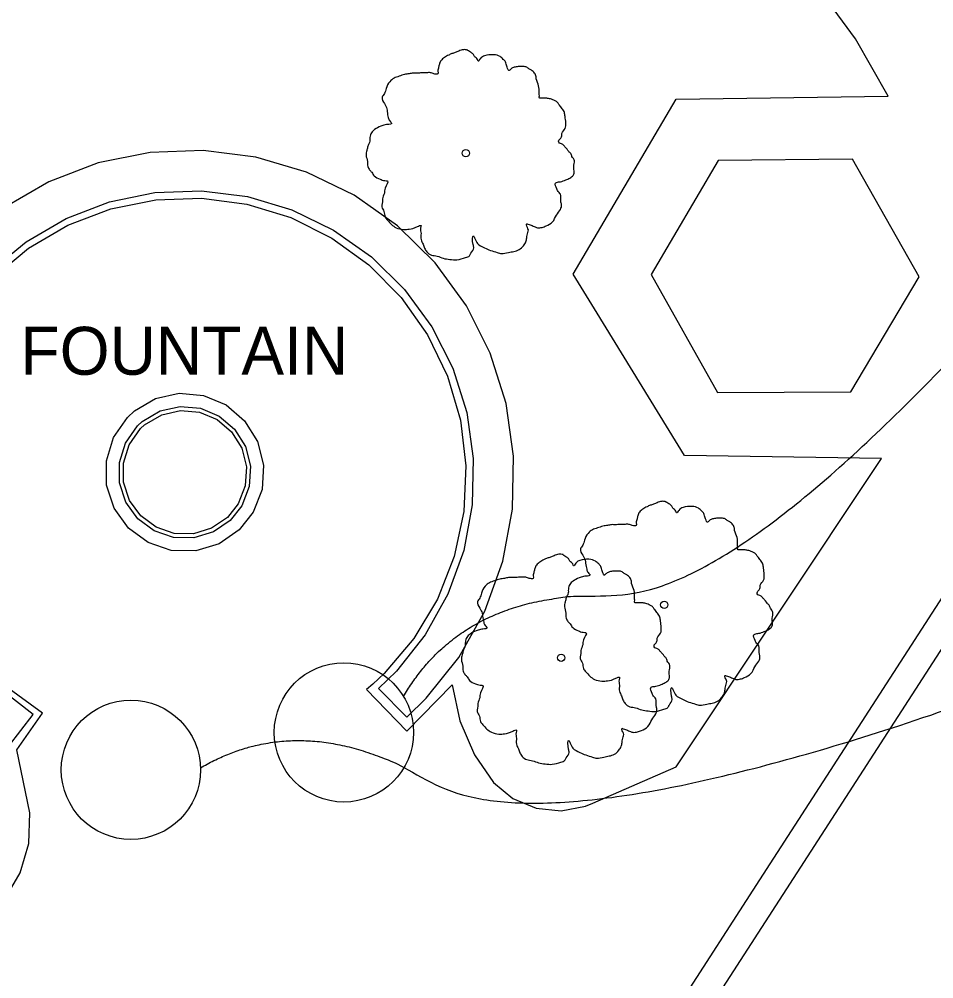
# Model space of a CAD drawing. Extents: x 2161152 to 2175754, y 602179 to 617749.
# Drawn here: x 2162210.9 to 2162258.6, y 604438.6 to 604488.6 of the extents above; entities that cross this region are included whole.
import ezdxf

# ---------------------------------------------------------------- set-up
doc = ezdxf.new("R2010")
doc.units = 0
for name, color, linetype in [('RD_EX_BldgApp', 7, 'Continuous'), ('RD_EX_BldgApp_Flagpole', 7, 'Continuous'), ('RD_EX_Conc_Curb', 7, 'Continuous'), ('RD_EX_Conc_Gutter', 7, 'Continuous'), ('RD_EX_Conc_Sidewalk', 7, 'Continuous'), ('RD_EX_H2O', 7, 'Continuous'), ('RD_EX_Misc_Golf_Cartpath', 7, 'Continuous'), ('RD_EX_VEG', 7, 'Continuous'), ('RD_EX_Wall', 7, 'Continuous')]:
    doc.layers.add(name, color=color, linetype=linetype)

msp = doc.modelspace()

# ---------------------------------------------------------------- linework, layer by layer
at = {"layer": 'RD_EX_BldgApp'}
msp.add_lwpolyline([(2162243.863, 604475.311), (2162247.306, 604469.159), (2162254.276, 604469.198), (2162257.836, 604475.18), (2162254.354, 604481.315), (2162247.346, 604481.257), (2162243.863, 604475.311)], dxfattribs=at)
at = {"layer": 'RD_EX_BldgApp_Flagpole'}
for centre in [(2162227.831, 604451.442), (2162216.724, 604449.493)]:
    msp.add_circle(centre, 3.63, dxfattribs=at)
for points in [[(2162230.941, 604453.313), (2162234.106, 604458.743), (2162249.321, 604458.429), (2162266.88, 604479.198)], [(2162220.352, 604449.592), (2162225.779, 604452.763), (2162238.871, 604445.006), (2162264.375, 604454.452)]]:
    msp.add_open_spline(points, degree=2, dxfattribs=at)
at = {"layer": 'RD_EX_Conc_Curb'}
msp.add_lwpolyline([(2162240.871, 604430.352), (2162249.525, 604443.766), (2162268.986, 604473.868)], dxfattribs=at)
at = {"layer": 'RD_EX_Conc_Gutter'}
msp.add_lwpolyline([(2162338.896, 604578.859), (2162334.64, 604572.384), (2162329.631, 604564.647), (2162322.947, 604554.413), (2162316.413, 604544.306), (2162296.019, 604512.784), (2162288.632, 604501.472), (2162280.136, 604488.331), (2162270.18, 604473.091), (2162250.721, 604442.993), (2162242.043, 604429.589), (2162236.596, 604421.216), (2162236.323, 604420.826), (2162236.31, 604420.722), (2162236.347, 604420.624), (2162236.488, 604420.501), (2162244.988, 604420.081), (2162253.595, 604419.765), (2162254.868, 604419.339), (2162256.485, 604417.99), (2162252.027, 604411.045), (2162237.228, 604388.179), (2162236.054, 604388.939)], dxfattribs=at)
at = {"layer": 'RD_EX_Conc_Sidewalk'}
for points in [[(2162209.54, 604475.147), (2162211.378, 604476.675), (2162213.442, 604477.881), (2162215.676, 604478.731), (2162218.019, 604479.203), (2162220.408, 604479.283), (2162222.778, 604478.97), (2162225.064, 604478.273), (2162227.205, 604477.209), (2162229.141, 604475.808), (2162230.822, 604474.108), (2162232.2, 604472.156), (2162233.239, 604470.003), (2162233.91, 604467.709), (2162234.195, 604465.337), (2162234.087, 604462.949), (2162233.588, 604460.611), (2162232.712, 604458.388), (2162231.483, 604456.338), (2162229.934, 604454.518), (2162229.336, 604453.955), (2162229.014, 604453.683), (2162231.113, 604451.512), (2162233.483, 604453.925), (2162233.875, 604452.038), (2162234.641, 604450.271), (2162235.642, 604448.824), (2162236.644, 604447.995), (2162237.851, 604447.49), (2162239.154, 604447.355), (2162240.436, 604447.602), (2162240.816, 604447.756), (2162245.163, 604449.641), (2162255.861, 604465.725), (2162245.597, 604465.872), (2162241.043, 604473.286), (2162239.785, 604475.317), (2162245.164, 604484.453), (2162256.222, 604484.598), (2162254.514, 604487.589), (2162252.478, 604490.366)], [(2162210.144, 604442.758), (2162210.952, 604444.128), (2162211.399, 604445.653), (2162211.459, 604447.242), (2162210.773, 604450.538), (2162212.11, 604452.437), (2162210.183, 604453.851)]]:
    msp.add_lwpolyline(points, dxfattribs=at)
at = {"layer": 'RD_EX_H2O'}
msp.add_lwpolyline([(2162221.76, 604462.649), (2162220.936, 604462.085), (2162219.982, 604461.798), (2162218.986, 604461.815), (2162218.042, 604462.134), (2162217.239, 604462.725), (2162216.655, 604463.531), (2162216.343, 604464.478), (2162216.334, 604465.474), (2162216.628, 604466.425), (2162217.222, 604467.278), (2162217.437, 604467.478), (2162218.332, 604468.002), (2162219.304, 604468.221), (2162220.297, 604468.134), (2162221.217, 604467.749), (2162221.975, 604467.103), (2162222.502, 604466.256), (2162222.746, 604465.29), (2162222.684, 604464.296), (2162222.322, 604463.362), (2162221.76, 604462.649)], dxfattribs=at)
at = {"layer": 'RD_EX_VEG'}
for centre, radius in [((2162234.19, 604481.631), 0.188), ((2162234.181, 604481.616), 0.000075), ((2162244.536, 604458.09), 0.188), ((2162244.526, 604458.076), 0.000075), ((2162239.164, 604455.332), 0.188), ((2162239.154, 604455.317), 0.000075)]:
    msp.add_circle(centre, radius, dxfattribs=at)
for points in [[(2162234.289, 604487.006), (2162234.065, 604487.025), (2162233.821, 604486.95), (2162233.633, 604486.875), (2162233.465, 604486.819), (2162233.296, 604486.744), (2162233.071, 604486.612), (2162232.903, 604486.462), (2162232.809, 604486.275), (2162232.771, 604486.106), (2162232.734, 604485.9), (2162232.734, 604485.769), (2162232.64, 604485.75), (2162232.528, 604485.769), (2162232.34, 604485.825), (2162232.153, 604485.825), (2162231.965, 604485.825), (2162231.703, 604485.806), (2162231.441, 604485.806), (2162231.235, 604485.769), (2162230.991, 604485.732), (2162230.71, 604485.638), (2162230.447, 604485.544), (2162230.222, 604485.357), (2162230.035, 604485.001), (2162229.941, 604484.738), (2162229.829, 604484.551), (2162229.941, 604484.213), (2162230.073, 604483.951), (2162230.091, 604483.801), (2162230.147, 604483.483), (2162230.222, 604483.314), (2162230.316, 604483.164), (2162230.26, 604483.145), (2162229.979, 604483.108), (2162229.754, 604483.033), (2162229.435, 604482.864), (2162229.267, 604482.695), (2162229.192, 604482.452), (2162229.173, 604482.189), (2162229.098, 604482.039), (2162229.042, 604481.833), (2162229.023, 604481.777), (2162228.985, 604481.533), (2162229.06, 604481.196), (2162229.079, 604480.934), (2162229.173, 604480.765), (2162229.285, 604480.634), (2162229.417, 604480.446), (2162229.716, 604480.278), (2162229.96, 604480.203), (2162230.11, 604480.184), (2162229.979, 604479.809), (2162229.941, 604479.547), (2162229.848, 604479.247), (2162229.848, 604479.191), (2162229.81, 604478.835), (2162229.923, 604478.591), (2162229.979, 604478.31), (2162230.11, 604478.141), (2162230.316, 604477.916), (2162230.56, 604477.748), (2162230.935, 604477.654), (2162231.235, 604477.673), (2162231.666, 604477.804), (2162231.853, 604477.86), (2162231.834, 604477.729), (2162231.853, 604477.448), (2162231.853, 604477.129), (2162231.965, 604476.885), (2162232.04, 604476.679), (2162232.153, 604476.492), (2162232.397, 604476.323), (2162232.696, 604476.267), (2162233.015, 604476.154), (2162233.352, 604476.098), (2162233.727, 604476.079), (2162234.177, 604476.192), (2162234.383, 604476.286), (2162234.458, 604476.417), (2162234.608, 604476.698), (2162234.571, 604476.867), (2162234.589, 604477.316), (2162234.664, 604477.185), (2162234.795, 604476.923), (2162235.17, 604476.698), (2162235.47, 604476.567), (2162235.826, 604476.454), (2162236.051, 604476.398), (2162236.407, 604476.454), (2162236.688, 604476.511), (2162236.969, 604476.604), (2162237.194, 604476.81), (2162237.326, 604477.017), (2162237.363, 604477.223), (2162237.419, 604477.504), (2162237.457, 604477.635)], [(2162237.457, 604477.635), (2162237.401, 604477.766), (2162237.363, 604477.954), (2162237.419, 604477.935), (2162237.55, 604477.897), (2162237.757, 604477.804), (2162237.925, 604477.748), (2162238.169, 604477.766), (2162238.375, 604477.841), (2162238.712, 604478.047), (2162238.919, 604478.403), (2162239.125, 604478.703), (2162239.181, 604478.947), (2162239.144, 604479.116), (2162239.125, 604479.49), (2162238.975, 604479.678), (2162238.937, 604479.772), (2162238.862, 604480.071), (2162238.919, 604480.109), (2162239.125, 604480.146), (2162239.406, 604480.24), (2162239.612, 604480.334), (2162239.781, 604480.465), (2162239.837, 604480.634), (2162239.818, 604480.934), (2162239.856, 604481.233), (2162239.8, 604481.346), (2162239.725, 604481.458), (2162239.668, 604481.608), (2162239.556, 604481.721), (2162239.481, 604481.833), (2162239.406, 604481.908), (2162239.312, 604482.021), (2162239.181, 604482.114), (2162239.069, 604482.152), (2162239.031, 604482.264), (2162239.144, 604482.414), (2162239.181, 604482.489), (2162239.2, 604482.658), (2162239.368, 604482.92), (2162239.406, 604483.22), (2162239.368, 604483.539), (2162239.331, 604483.745), (2162239.218, 604483.951), (2162239.069, 604484.138), (2162238.975, 604484.27), (2162238.844, 604484.363), (2162238.6, 604484.457), (2162238.413, 604484.495), (2162238.15, 604484.495), (2162238, 604484.532), (2162238.019, 604484.57), (2162238.019, 604484.682), (2162238.019, 604484.888), (2162237.963, 604485.225), (2162237.85, 604485.6), (2162237.85, 604485.619), (2162237.775, 604485.806), (2162237.607, 604485.956), (2162237.476, 604486.031), (2162237.326, 604486.125), (2162237.138, 604486.144), (2162236.913, 604486.144), (2162236.707, 604486.106), (2162236.557, 604486.031), (2162236.426, 604485.938), (2162236.37, 604486.05), (2162236.295, 604486.275), (2162236.257, 604486.387), (2162236.145, 604486.519), (2162235.976, 604486.669), (2162235.639, 604486.762), (2162235.17, 604486.706), (2162234.945, 604486.556), (2162234.833, 604486.425), (2162234.795, 604486.519), (2162234.645, 604486.669), (2162234.571, 604486.8), (2162234.439, 604486.894), (2162234.327, 604486.968), (2162234.252, 604487.006)], [(2162244.635, 604463.466), (2162244.41, 604463.484), (2162244.166, 604463.409), (2162243.979, 604463.334), (2162243.81, 604463.278), (2162243.641, 604463.203), (2162243.416, 604463.072), (2162243.248, 604462.922), (2162243.154, 604462.735), (2162243.117, 604462.566), (2162243.079, 604462.36), (2162243.079, 604462.229), (2162242.985, 604462.21), (2162242.873, 604462.229), (2162242.686, 604462.285), (2162242.498, 604462.285), (2162242.311, 604462.285), (2162242.048, 604462.266), (2162241.786, 604462.266), (2162241.58, 604462.229), (2162241.336, 604462.191), (2162241.055, 604462.097), (2162240.793, 604462.004), (2162240.568, 604461.816), (2162240.38, 604461.46), (2162240.287, 604461.198), (2162240.174, 604461.01), (2162240.287, 604460.673), (2162240.418, 604460.411), (2162240.436, 604460.261), (2162240.493, 604459.942), (2162240.568, 604459.773), (2162240.661, 604459.623), (2162240.605, 604459.605), (2162240.324, 604459.567), (2162240.099, 604459.492), (2162239.781, 604459.324), (2162239.612, 604459.155), (2162239.537, 604458.911), (2162239.518, 604458.649), (2162239.443, 604458.499), (2162239.387, 604458.293), (2162239.368, 604458.237), (2162239.331, 604457.993), (2162239.406, 604457.656), (2162239.424, 604457.393), (2162239.518, 604457.225), (2162239.631, 604457.093), (2162239.762, 604456.906), (2162240.062, 604456.737), (2162240.305, 604456.662), (2162240.455, 604456.644), (2162240.324, 604456.269), (2162240.287, 604456.006), (2162240.193, 604455.706), (2162240.193, 604455.65), (2162240.155, 604455.294), (2162240.268, 604455.05), (2162240.324, 604454.769), (2162240.455, 604454.601), (2162240.661, 604454.376), (2162240.905, 604454.207), (2162241.28, 604454.113), (2162241.58, 604454.132), (2162242.011, 604454.263), (2162242.198, 604454.32), (2162242.179, 604454.188), (2162242.198, 604453.907), (2162242.198, 604453.589), (2162242.311, 604453.345), (2162242.386, 604453.139), (2162242.498, 604452.951), (2162242.742, 604452.783), (2162243.042, 604452.727), (2162243.36, 604452.614), (2162243.698, 604452.558), (2162244.072, 604452.539), (2162244.522, 604452.652), (2162244.728, 604452.745), (2162244.803, 604452.876), (2162244.953, 604453.158), (2162244.916, 604453.326), (2162244.935, 604453.776), (2162245.009, 604453.645), (2162245.141, 604453.382), (2162245.516, 604453.158), (2162245.815, 604453.026), (2162246.171, 604452.914), (2162246.396, 604452.858), (2162246.752, 604452.914), (2162247.034, 604452.97), (2162247.315, 604453.064), (2162247.54, 604453.27), (2162247.671, 604453.476), (2162247.708, 604453.682), (2162247.765, 604453.963), (2162247.802, 604454.095)], [(2162247.802, 604454.095), (2162247.746, 604454.226), (2162247.708, 604454.413), (2162247.765, 604454.395), (2162247.896, 604454.357), (2162248.102, 604454.263), (2162248.271, 604454.207), (2162248.514, 604454.226), (2162248.72, 604454.301), (2162249.058, 604454.507), (2162249.264, 604454.863), (2162249.47, 604455.163), (2162249.526, 604455.407), (2162249.489, 604455.575), (2162249.47, 604455.95), (2162249.32, 604456.138), (2162249.283, 604456.231), (2162249.208, 604456.531), (2162249.264, 604456.569), (2162249.47, 604456.606), (2162249.751, 604456.7), (2162249.957, 604456.793), (2162250.126, 604456.925), (2162250.182, 604457.093), (2162250.164, 604457.393), (2162250.201, 604457.693), (2162250.145, 604457.806), (2162250.07, 604457.918), (2162250.014, 604458.068), (2162249.901, 604458.18), (2162249.826, 604458.293), (2162249.751, 604458.368), (2162249.657, 604458.48), (2162249.526, 604458.574), (2162249.414, 604458.611), (2162249.376, 604458.724), (2162249.489, 604458.874), (2162249.526, 604458.949), (2162249.545, 604459.117), (2162249.714, 604459.38), (2162249.751, 604459.68), (2162249.714, 604459.998), (2162249.676, 604460.205), (2162249.564, 604460.411), (2162249.414, 604460.598), (2162249.32, 604460.729), (2162249.189, 604460.823), (2162248.945, 604460.917), (2162248.758, 604460.954), (2162248.495, 604460.954), (2162248.346, 604460.992), (2162248.364, 604461.029), (2162248.364, 604461.142), (2162248.364, 604461.348), (2162248.308, 604461.685), (2162248.196, 604462.06), (2162248.196, 604462.079), (2162248.121, 604462.266), (2162247.952, 604462.416), (2162247.821, 604462.491), (2162247.671, 604462.585), (2162247.483, 604462.603), (2162247.259, 604462.603), (2162247.052, 604462.566), (2162246.902, 604462.491), (2162246.771, 604462.397), (2162246.715, 604462.51), (2162246.64, 604462.735), (2162246.603, 604462.847), (2162246.49, 604462.978), (2162246.321, 604463.128), (2162245.984, 604463.222), (2162245.516, 604463.166), (2162245.291, 604463.016), (2162245.178, 604462.885), (2162245.141, 604462.978), (2162244.991, 604463.128), (2162244.916, 604463.259), (2162244.785, 604463.353), (2162244.672, 604463.428), (2162244.597, 604463.466)], [(2162239.263, 604460.707), (2162239.038, 604460.726), (2162238.794, 604460.651), (2162238.607, 604460.576), (2162238.438, 604460.52), (2162238.269, 604460.445), (2162238.045, 604460.313), (2162237.876, 604460.163), (2162237.782, 604459.976), (2162237.745, 604459.807), (2162237.707, 604459.601), (2162237.707, 604459.47), (2162237.614, 604459.451), (2162237.501, 604459.47), (2162237.314, 604459.526), (2162237.126, 604459.526), (2162236.939, 604459.526), (2162236.676, 604459.507), (2162236.414, 604459.507), (2162236.208, 604459.47), (2162235.964, 604459.433), (2162235.683, 604459.339), (2162235.421, 604459.245), (2162235.196, 604459.058), (2162235.008, 604458.702), (2162234.915, 604458.439), (2162234.802, 604458.252), (2162234.915, 604457.914), (2162235.046, 604457.652), (2162235.065, 604457.502), (2162235.121, 604457.184), (2162235.196, 604457.015), (2162235.29, 604456.865), (2162235.233, 604456.846), (2162234.952, 604456.809), (2162234.727, 604456.734), (2162234.409, 604456.565), (2162234.24, 604456.396), (2162234.165, 604456.153), (2162234.146, 604455.89), (2162234.071, 604455.74), (2162234.015, 604455.534), (2162233.996, 604455.478), (2162233.959, 604455.234), (2162234.034, 604454.897), (2162234.053, 604454.635), (2162234.146, 604454.466), (2162234.259, 604454.335), (2162234.39, 604454.147), (2162234.69, 604453.979), (2162234.933, 604453.904), (2162235.083, 604453.885), (2162234.952, 604453.51), (2162234.915, 604453.248), (2162234.821, 604452.948), (2162234.821, 604452.892), (2162234.784, 604452.536), (2162234.896, 604452.292), (2162234.952, 604452.011), (2162235.083, 604451.842), (2162235.29, 604451.617), (2162235.533, 604451.449), (2162235.908, 604451.355), (2162236.208, 604451.374), (2162236.639, 604451.505), (2162236.826, 604451.561), (2162236.808, 604451.43), (2162236.826, 604451.149), (2162236.826, 604450.83), (2162236.939, 604450.586), (2162237.014, 604450.38), (2162237.126, 604450.193), (2162237.37, 604450.024), (2162237.67, 604449.968), (2162237.988, 604449.855), (2162238.326, 604449.799), (2162238.701, 604449.78), (2162239.15, 604449.893), (2162239.356, 604449.987), (2162239.431, 604450.118), (2162239.581, 604450.399), (2162239.544, 604450.568), (2162239.563, 604451.017), (2162239.638, 604450.886), (2162239.769, 604450.624), (2162240.144, 604450.399), (2162240.444, 604450.268), (2162240.8, 604450.155), (2162241.025, 604450.099), (2162241.381, 604450.155), (2162241.662, 604450.212), (2162241.943, 604450.305), (2162242.168, 604450.511), (2162242.299, 604450.718), (2162242.336, 604450.924), (2162242.393, 604451.205), (2162242.43, 604451.336)], [(2162242.43, 604451.336), (2162242.374, 604451.467), (2162242.336, 604451.655), (2162242.393, 604451.636), (2162242.524, 604451.598), (2162242.73, 604451.505), (2162242.899, 604451.449), (2162243.142, 604451.467), (2162243.349, 604451.542), (2162243.686, 604451.748), (2162243.892, 604452.104), (2162244.098, 604452.404), (2162244.154, 604452.648), (2162244.117, 604452.817), (2162244.098, 604453.191), (2162243.948, 604453.379), (2162243.911, 604453.473), (2162243.836, 604453.772), (2162243.892, 604453.81), (2162244.098, 604453.847), (2162244.379, 604453.941), (2162244.585, 604454.035), (2162244.754, 604454.166), (2162244.81, 604454.335), (2162244.792, 604454.635), (2162244.829, 604454.934), (2162244.773, 604455.047), (2162244.698, 604455.159), (2162244.642, 604455.309), (2162244.529, 604455.422), (2162244.454, 604455.534), (2162244.379, 604455.609), (2162244.286, 604455.722), (2162244.154, 604455.815), (2162244.042, 604455.853), (2162244.004, 604455.965), (2162244.117, 604456.115), (2162244.154, 604456.19), (2162244.173, 604456.359), (2162244.342, 604456.621), (2162244.379, 604456.921), (2162244.342, 604457.24), (2162244.304, 604457.446), (2162244.192, 604457.652), (2162244.042, 604457.839), (2162243.948, 604457.971), (2162243.817, 604458.064), (2162243.573, 604458.158), (2162243.386, 604458.196), (2162243.124, 604458.196), (2162242.974, 604458.233), (2162242.992, 604458.271), (2162242.992, 604458.383), (2162242.992, 604458.589), (2162242.936, 604458.926), (2162242.824, 604459.301), (2162242.824, 604459.32), (2162242.749, 604459.507), (2162242.58, 604459.657), (2162242.449, 604459.732), (2162242.299, 604459.826), (2162242.112, 604459.845), (2162241.887, 604459.845), (2162241.68, 604459.807), (2162241.531, 604459.732), (2162241.399, 604459.639), (2162241.343, 604459.751), (2162241.268, 604459.976), (2162241.231, 604460.088), (2162241.118, 604460.22), (2162240.95, 604460.37), (2162240.612, 604460.463), (2162240.144, 604460.407), (2162239.919, 604460.257), (2162239.806, 604460.126), (2162239.769, 604460.22), (2162239.619, 604460.37), (2162239.544, 604460.501), (2162239.413, 604460.595), (2162239.3, 604460.669), (2162239.225, 604460.707)]]:
    msp.add_spline(points, degree=3, dxfattribs=at)
at = {"layer": 'RD_EX_Wall'}
for points in [[(2162229.639, 604453.736), (2162231.107, 604452.229), (2162232.129, 604453.225), (2162233.827, 604455.354), (2162235.177, 604457.765), (2162236.118, 604460.363), (2162236.624, 604463.079), (2162236.684, 604465.842), (2162236.294, 604468.577), (2162235.466, 604471.213), (2162234.221, 604473.68), (2162232.593, 604475.911), (2162230.624, 604477.849), (2162228.366, 604479.442), (2162225.88, 604480.647), (2162223.232, 604481.432), (2162220.491, 604481.778), (2162217.73, 604481.673), (2162215.023, 604481.122), (2162212.441, 604480.139), (2162210.053, 604478.75)], [(2162209.393, 604475.478), (2162211.259, 604477.018), (2162213.35, 604478.234), (2162215.611, 604479.095), (2162217.981, 604479.577), (2162220.398, 604479.668), (2162222.798, 604479.366), (2162225.117, 604478.678), (2162227.294, 604477.623), (2162229.27, 604476.229), (2162230.994, 604474.532), (2162232.42, 604472.578), (2162233.51, 604470.418), (2162234.235, 604468.11), (2162234.576, 604465.715), (2162234.524, 604463.296), (2162234.081, 604460.918), (2162233.257, 604458.643), (2162232.075, 604456.532), (2162230.567, 604454.64), (2162229.639, 604453.736)], [(2162222.374, 604461.994), (2162221.324, 604461.274), (2162220.105, 604460.908), (2162218.833, 604460.93), (2162217.627, 604461.337), (2162216.602, 604462.092), (2162215.855, 604463.122), (2162215.457, 604464.331), (2162215.445, 604465.604), (2162215.821, 604466.819), (2162216.548, 604467.863), (2162216.904, 604468.194), (2162218.003, 604468.838), (2162219.245, 604469.117), (2162220.513, 604469.006), (2162221.687, 604468.514), (2162222.656, 604467.689), (2162223.328, 604466.608), (2162223.64, 604465.374), (2162223.562, 604464.103), (2162223.101, 604462.917), (2162222.374, 604461.994)], [(2162221.905, 604462.495), (2162221.028, 604461.893), (2162220.011, 604461.588), (2162218.95, 604461.606), (2162217.944, 604461.946), (2162217.089, 604462.575), (2162216.466, 604463.435), (2162216.134, 604464.443), (2162216.124, 604465.504), (2162216.437, 604466.518), (2162217.063, 604467.416), (2162217.311, 604467.647), (2162218.254, 604468.2), (2162219.29, 604468.433), (2162220.348, 604468.34), (2162221.328, 604467.93), (2162222.136, 604467.241), (2162222.697, 604466.339), (2162222.957, 604465.31), (2162222.892, 604464.25), (2162222.506, 604463.257), (2162221.905, 604462.495)], [(2162210.343, 604450.708), (2162211.631, 604452.371), (2162209.719, 604453.853)]]:
    msp.add_lwpolyline(points, dxfattribs=at)

# ---------------------------------------------------------------- texts
at = {"layer": 'RD_EX_Misc_Golf_Cartpath'}
msp.add_text('FOUNTAIN', height=2.5, dxfattribs=at).set_placement((2162210.971, 604470.081))

doc.saveas('drawing.dxf')
